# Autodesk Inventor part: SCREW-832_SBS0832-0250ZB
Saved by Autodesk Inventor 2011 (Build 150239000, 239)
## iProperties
Created: 2007-10
Part Number: SCREW-832_SBS0832-0250ZB
Document SubType Name: Modeling
Density: 1 g/cm^3
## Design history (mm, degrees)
feature "Base1"
body "Solid1"
